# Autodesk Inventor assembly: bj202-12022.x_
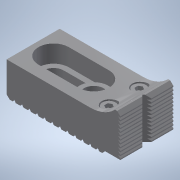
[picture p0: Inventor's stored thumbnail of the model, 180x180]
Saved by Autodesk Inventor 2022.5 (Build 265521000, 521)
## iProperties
Part Number: bj202-12022.x_
Material: 一般
Document SubType Name: Assembly
Designer: ImaoCorp
Sending System: SOLIDWORKS 2017-2017317
MC: AMD64
MC_MODEL: Intel64 Family 6 Model 60 Stepping 3, GenuineIntel
OS: Windows_NT
FRU: Parasolid Version 29.0, build 201,  4-17-2017
FORMAT: text
GUISE: transmit
KEY: bj202-12022
FILE: bj202-12022.x_t
DATE: Fri Mar 15 10:16:20 2019
Author: ImaoCorp
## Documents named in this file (3)
- X:\14_SW2022-Inv2022\00_全2023-1023新製品(TCC)まで\b\bj202-12022\BJ202-12022.iam
- X:\14_SW2022-Inv2022\00_全2023-1023新製品(TCC)まで\b\bj202-12022\bj202-12022_01.ipt
- X:\14_SW2022-Inv2022\00_全2023-1023新製品(TCC)まで\b\bj202-12022\bj202-12022_02.ipt
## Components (2 placed, 2 different names)
1. bj202-12022_01
2. bj202-12022_02
